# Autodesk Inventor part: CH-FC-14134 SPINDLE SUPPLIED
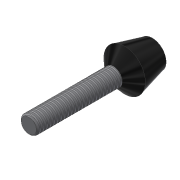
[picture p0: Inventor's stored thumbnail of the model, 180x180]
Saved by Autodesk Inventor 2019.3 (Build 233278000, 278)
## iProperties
Created: 2015-08
Part Number: CH-FC-14134 SPINDLE SUPPLIED
Material: Ogólny
Document SubType Name: Modeling
Designer: CADENGINEERING4
Density: 1 g/cm^3
Appearance: Domyślna
Author: CADENGINEERING4
Revision Number: ÈÎºÎ
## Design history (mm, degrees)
feature "NONE"
node "Bryła1"
